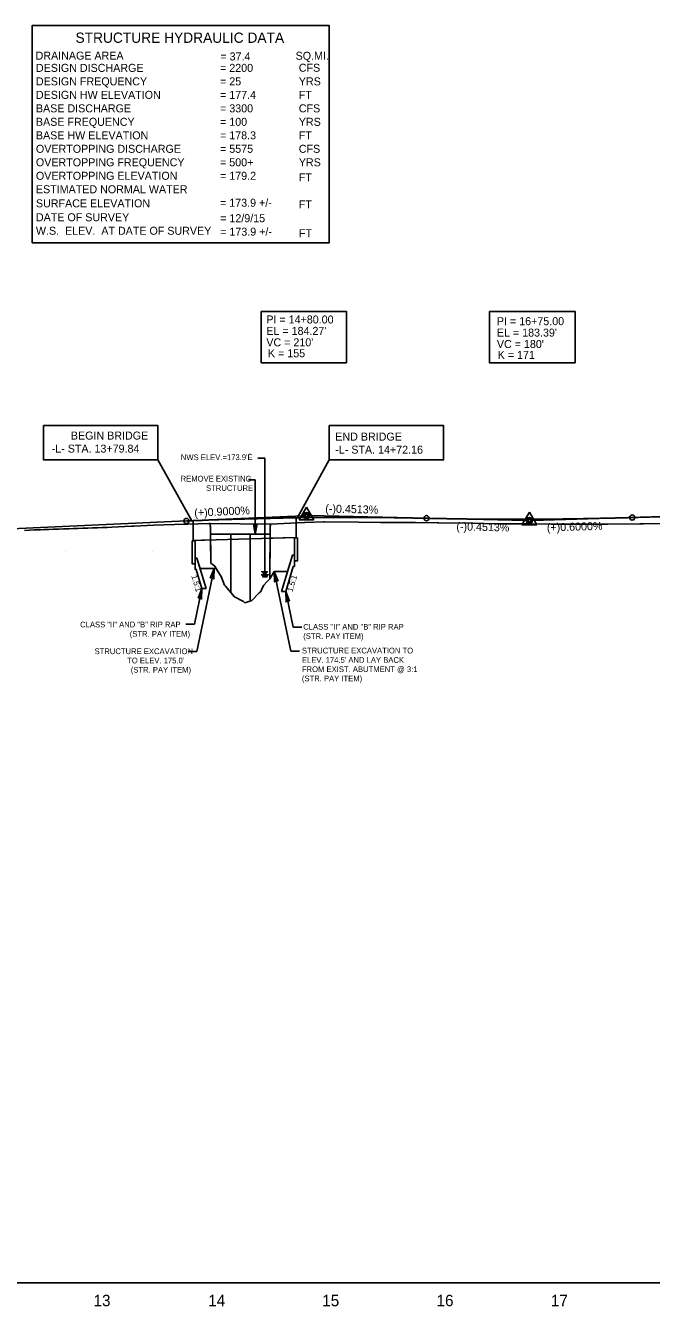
# Model space of a CAD drawing. Extents: x 1726619 to 1729848, y 535683 to 539687.
# Drawn here: x 1728544 to 1729092, y 537992 to 539113 of the extents above; entities that cross this region are included whole.
import ezdxf

# ---------------------------------------------------------------- set-up
doc = ezdxf.new("R2010")
doc.units = 0
for name, color, linetype in [('COGO Default Spiral', 7, 'Continuous'), ('Exist Drainage Structure Bridge', 7, 'Continuous'), ('Exist Profile Cell', 7, 'Continuous'), ('Exist Vertical Profile Horizontal Axis Label Major', 7, 'Continuous'), ('Exist Vertical Profile Horizontal Axis Label Minor', 7, 'Continuous'), ('Exist Vertical Profile Vertical Axis Label', 7, 'Continuous'), ('Prop Dimension', 7, 'Continuous'), ('Prop Dimension Text', 7, 'Continuous'), ('Prop Drainage Structure Bridge Opening Label', 7, 'Continuous'), ('Prop PFL Structure Hydraulic Data Label CELL', 7, 'Continuous'), ('Prop Terminator CELL', 7, 'Continuous'), ('Prop Vertical Profile Grade', 7, 'Continuous'), ('Raster_Level_0', 7, 'Continuous'), ('Sheet Cutting Line CELL', 7, 'Continuous'), ('Sheet Profile CELL', 7, 'Continuous'), ('Sheet Profile Grid Major CELL', 7, 'Continuous'), ('Sheet Profile Grid Middle CELL', 7, 'Continuous'), ('Sheet Profile Grid Minor CELL', 7, 'Continuous'), ('Sheet Sticker Incomplete CELL', 7, 'Continuous')]:
    doc.layers.add(name, color=color, linetype=linetype)

msp = doc.modelspace()

# ---------------------------------------------------------------- linework, layer by layer
at = {"layer": 'COGO Default Spiral'}
for p, q in [((1728747.4, 538734.4), (1728753.4, 538734.4)), ((1728753.4, 538632.5), (1728753.4, 538734.4)), ((1728745.1, 538715.5), (1728739.2, 538715.5)), ((1728745.1, 538668), (1728745.1, 538715.5))]:
    msp.add_line(p, q, dxfattribs=at)
for points in [[(1728753.4, 538632.5), (1728756.5, 538632.5), (1728750.4, 538632.5)], [(1728753.4, 538631.6), (1728755.8, 538631.6), (1728751, 538631.6)], [(1728753.4, 538630.7), (1728755.3, 538630.7), (1728751.5, 538630.7)]]:
    msp.add_lwpolyline(points, dxfattribs=at)
msp.add_lwpolyline([(1728753.4, 538632.5), (1728750.8, 538635.1), (1728755.7, 538635.1)], close=True, dxfattribs=at)
at = {"layer": 'Exist Drainage Structure Bridge'}
for p, q in [((1728705.6, 538677.4), (1728758.4, 538676.9)), ((1728706, 538668), (1728758.1, 538668)), ((1728723.6, 538616.8), (1728723.6, 538668)), ((1728740.6, 538609.6), (1728740.6, 538668))]:
    msp.add_line(p, q, dxfattribs=at)
at = {"layer": 'Exist Profile Cell'}
msp.add_line((1728309.9, 538013), (1729848.2, 538013), dxfattribs=at)
at = {"layer": 'Exist Vertical Profile Horizontal Axis Label Major'}
msp.add_line((1728439.9, 538668.6), (1728684.9, 538679.6), dxfattribs=at)
for points in [[(1728684.9, 538679.6), (1728689.1, 538679.8), (1728693.3, 538680), (1728697.5, 538680.1), (1728701.7, 538680.3), (1728705.9, 538680.5), (1728710.1, 538680.6), (1728714.3, 538680.8), (1728718.5, 538680.9), (1728722.7, 538681.1), (1728726.9, 538681.2), (1728731.1, 538681.3), (1728735.3, 538681.5), (1728739.5, 538681.6), (1728743.7, 538681.7), (1728747.9, 538681.8), (1728752.1, 538681.9), (1728756.3, 538682), (1728760.5, 538682.1), (1728764.7, 538682.2), (1728768.9, 538682.2), (1728773.1, 538682.3), (1728777.3, 538682.4), (1728781.5, 538682.4), (1728785.7, 538682.5), (1728789.9, 538682.5), (1728794.1, 538682.6), (1728798.3, 538682.6), (1728802.5, 538682.7), (1728806.7, 538682.7), (1728810.9, 538682.7), (1728815.1, 538682.7), (1728819.3, 538682.7), (1728823.5, 538682.7), (1728827.7, 538682.7), (1728831.9, 538682.7), (1728836.1, 538682.7), (1728840.3, 538682.7), (1728844.5, 538682.7), (1728848.7, 538682.7), (1728852.9, 538682.6), (1728857.1, 538682.6), (1728861.3, 538682.5), (1728865.5, 538682.5), (1728869.7, 538682.4), (1728873.9, 538682.4), (1728878.1, 538682.3), (1728882.3, 538682.2), (1728886.5, 538682.1), (1728890.7, 538682), (1728894.9, 538682)], [(1728894.9, 538682), (1728898.5, 538681.9), (1728902.1, 538681.8), (1728905.7, 538681.7), (1728909.3, 538681.7), (1728912.9, 538681.6), (1728916.5, 538681.5), (1728920.1, 538681.5), (1728923.7, 538681.4), (1728927.3, 538681.4), (1728930.9, 538681.3), (1728934.5, 538681.3), (1728938.1, 538681.3), (1728941.7, 538681.2), (1728945.3, 538681.2), (1728948.9, 538681.2), (1728952.5, 538681.1), (1728956.1, 538681.1), (1728959.7, 538681.1), (1728963.3, 538681.1), (1728966.9, 538681.1), (1728970.5, 538681.1), (1728974.1, 538681.1), (1728977.7, 538681.1), (1728981.3, 538681.1), (1728984.9, 538681.1), (1728988.5, 538681.1), (1728992.1, 538681.1), (1728995.7, 538681.2), (1728999.3, 538681.2), (1729002.9, 538681.2), (1729006.5, 538681.3), (1729010.1, 538681.3), (1729013.7, 538681.3), (1729017.3, 538681.4), (1729020.9, 538681.4), (1729024.5, 538681.5), (1729028.1, 538681.5), (1729031.7, 538681.6), (1729035.3, 538681.7), (1729038.9, 538681.7), (1729042.5, 538681.8), (1729046.1, 538681.9), (1729049.7, 538682), (1729053.3, 538682), (1729056.9, 538682.1), (1729060.5, 538682.2), (1729064.1, 538682.3), (1729067.7, 538682.4), (1729071.3, 538682.5), (1729074.9, 538682.6)], [(1729074.9, 538682.6), (1729081.7, 538682.8), (1729088.5, 538683), (1729095.3, 538683.2), (1729102.1, 538683.3), (1729108.9, 538683.5), (1729115.7, 538683.6), (1729122.5, 538683.7), (1729129.3, 538683.8), (1729136.1, 538683.8), (1729142.9, 538683.9), (1729149.7, 538683.9), (1729156.5, 538684), (1729163.3, 538684), (1729170.1, 538684), (1729176.9, 538684), (1729183.7, 538683.9), (1729190.5, 538683.9), (1729197.3, 538683.8), (1729204.1, 538683.8), (1729210.9, 538683.7), (1729217.7, 538683.6), (1729224.5, 538683.4), (1729231.3, 538683.3), (1729238.1, 538683.1), (1729244.9, 538683), (1729251.7, 538682.8), (1729258.5, 538682.6), (1729265.3, 538682.4), (1729272.1, 538682.1), (1729278.9, 538681.9), (1729285.7, 538681.6), (1729292.5, 538681.4), (1729299.3, 538681.1), (1729306.1, 538680.8), (1729312.9, 538680.4), (1729319.7, 538680.1), (1729326.5, 538679.8), (1729333.3, 538679.4), (1729340.1, 538679), (1729346.9, 538678.6), (1729353.7, 538678.2), (1729360.5, 538677.8), (1729367.3, 538677.3), (1729374.1, 538676.9), (1729380.9, 538676.4), (1729387.7, 538675.9), (1729394.5, 538675.4), (1729401.3, 538674.9), (1729408.1, 538674.4), (1729414.9, 538673.8)]]:
    msp.add_spline(points, degree=3, dxfattribs=at)
at = {"layer": 'Exist Vertical Profile Horizontal Axis Label Minor'}
for p, q in [((1728579.2, 538653.1), (1728579.2, 538653.1)), ((1728655.6, 538653.1), (1728655.6, 538653.1))]:
    msp.add_line(p, q, dxfattribs=at)
at = {"layer": 'Exist Vertical Profile Vertical Axis Label'}
for p, q in [((1728659.9, 538733), (1728689.7, 538679.8)), ((1728809.9, 538733), (1728782.1, 538682.5)), ((1729074.9, 538682.6), (1729242.1, 538687.6)), ((1728684.9, 538679.6), (1728787.1, 538684.2)), ((1728894.9, 538682), (1728792.6, 538684.3)), ((1728894.9, 538682), (1728982.1, 538680)), ((1729074.9, 538682.6), (1728987.6, 538680))]:
    msp.add_line(p, q, dxfattribs=at)
for centre in [(1728789.9, 538684.3), (1728984.9, 538679.9)]:
    msp.add_circle(centre, 2.75, dxfattribs=at)
at = {"layer": 'Prop Dimension'}
for p, q in [((1728709.1, 538638), (1728694, 538565.5)), ((1728761.7, 538635.5), (1728776.3, 538565.6)), ((1728698.5, 538620.5), (1728692, 538589.2)), ((1728771.7, 538618), (1728778.3, 538586.7)), ((1728692, 538589.2), (1728684.4, 538589.2)), ((1728778.3, 538586.7), (1728785.8, 538586.7)), ((1728694, 538565.5), (1728686.4, 538565.5)), ((1728776.3, 538565.6), (1728783.8, 538565.6))]:
    msp.add_line(p, q, dxfattribs=at)
at = {"layer": 'Prop Terminator CELL'}
for points in [[(1728743.7, 538677), (1728745.1, 538668), (1728746.9, 538677), (1728745.3, 538675.9)], [(1728705.7, 538629.5), (1728709.1, 538638), (1728708.8, 538628.8), (1728707.5, 538630.2)], [(1728765.1, 538627), (1728761.7, 538635.5), (1728762, 538626.3), (1728763.3, 538627.7)], [(1728695.2, 538612), (1728698.5, 538620.5), (1728698.2, 538611.3), (1728696.9, 538612.7)], [(1728775.1, 538609.5), (1728771.7, 538618), (1728772, 538608.8), (1728773.4, 538610.2)]]:
    msp.add_lwpolyline(points, close=True, dxfattribs=at)
at = {"layer": 'Prop Vertical Profile Grade'}
msp.add_lwpolyline([(1728543.2, 538671.4), (1728547.5, 538671.5), (1728551.7, 538671.7), (1728556, 538671.8), (1728557.2, 538671.9), (1728560.2, 538672), (1728564.5, 538672.1), (1728568.7, 538672.3), (1728573, 538672.5), (1728577.2, 538672.6), (1728581.5, 538672.8), (1728582, 538672.8), (1728585.7, 538672.9), (1728590, 538673.1), (1728594.2, 538673.2), (1728598.5, 538673.4), (1728602.7, 538673.5), (1728607, 538673.7), (1728611.2, 538673.8), (1728615.5, 538674), (1728619.7, 538674.2), (1728636.7, 538675), (1728639.2, 538675), (1728656.1, 538675.8), (1728683.6, 538676.7), (1728686.1, 538676.8), (1728704.4, 538677.4), (1728705.6, 538677.4), (1728705.7, 538674.8), (1728706, 538674.8), (1728706.1, 538642.7), (1728709.6, 538640), (1728712.1, 538635.9), (1728715.3, 538630.9), (1728718.2, 538623.5), (1728719, 538622.6), (1728726.8, 538613.2), (1728734.8, 538609), (1728736.1, 538608), (1728742.2, 538610.1), (1728748.4, 538616.7), (1728750.1, 538617.8), (1728751.5, 538621.3), (1728752.7, 538623.4), (1728755, 538626), (1728757.9, 538629.1), (1728758.1, 538675.4), (1728758.4, 538675.2), (1728758.4, 538676.9), (1728787.9, 538678.2), (1728788.4, 538678.2), (1728805.2, 538678.9), (1728805.5, 538678.9), (1728806.1, 538678.9), (1728835.5, 538678.6), (1728855, 538678.4), (1728855.4, 538678.4), (1728884.8, 538678.2), (1728885.4, 538678.2), (1728904.5, 538678.1), (1728905, 538678.1), (1728905.7, 538678.1), (1728935, 538677.6), (1728935.5, 538677.6), (1728954.6, 538677.2), (1728955.6, 538677.2), (1728984.6, 538677), (1728985.3, 538677), (1729004, 538676.9), (1729004.9, 538676.9), (1729033.9, 538676.9), (1729034.9, 538676.9), (1729053.5, 538676.9), (1729081.6, 538677.1), (1729083.5, 538677.1), (1729084.8, 538677.2), (1729103.1, 538677.3)], dxfattribs=at)
at = {"layer": 'Raster_Level_0'}
for p, q in [((1728780.9, 538665.1), (1728758.1, 538664.5)), ((1728780.9, 538664.7), (1728780.9, 538665.1)), ((1728706, 538663), (1728690.9, 538662.6)), ((1728690.9, 538662.6), (1728690.9, 538662.2)), ((1728710.9, 538638), (1728696.9, 538638)), ((1728696.9, 538638), (1728710.9, 538638)), ((1728757.9, 538629.1), (1728761.7, 538635.5)), ((1728757.9, 538629.1), (1728761.7, 538635.5)), ((1728761.7, 538635.5), (1728773.4, 538635.5)), ((1728761.7, 538635.5), (1728773.4, 538635.5)), ((1728698.5, 538620.5), (1728702.1, 538620.5)), ((1728768.1, 538618), (1728771.7, 538618))]:
    msp.add_line(p, q, dxfattribs=at)
for points in [[(1728758.1, 538664.5), (1728757.9, 538629.1)], [(1728779.3, 538649.7), (1728779.3, 538664.7), (1728780.9, 538664.7)], [(1728690.9, 538662.2), (1728692.5, 538662.2), (1728692.5, 538647.2)], [(1728710.9, 538638), (1728709.6, 538640), (1728706.1, 538642.7), (1728706, 538663)], [(1728702.1, 538620.5), (1728694.1, 538647.2), (1728692.5, 538647.2), (1728692.5, 538637.2), (1728693.5, 538637.2), (1728698.5, 538620.5)], [(1728692.5, 538647.2), (1728694.1, 538647.2), (1728696.9, 538638)], [(1728768.1, 538618), (1728777.7, 538649.7), (1728779.3, 538649.7), (1728779.3, 538639.7), (1728778.3, 538639.7), (1728771.7, 538618)], [(1728773.4, 538635.5), (1728777.7, 538649.7), (1728779.3, 538649.7)]]:
    msp.add_lwpolyline(points, dxfattribs=at)
at = {"layer": 'Sheet Profile CELL'}
for p, q in [((1728789.9, 538691.8), (1728783.4, 538680.6)), ((1728789.9, 538691.8), (1728796.4, 538680.6)), ((1728984.9, 538687.4), (1728978.4, 538676.2)), ((1728984.9, 538687.4), (1728991.4, 538676.2)), ((1728783.4, 538680.6), (1728796.4, 538680.6)), ((1728978.4, 538676.2), (1728991.4, 538676.2))]:
    msp.add_line(p, q, dxfattribs=at)
for centre, radius in [((1728789.9, 538684.3), 1.75), ((1728789.9, 538684.3), 1.2), ((1728984.9, 538679.9), 1.75), ((1728984.9, 538679.9), 1.2)]:
    msp.add_circle(centre, radius, dxfattribs=at)
at = {"layer": 'Sheet Profile Grid Major CELL'}
for points in [[(1728549.9, 538923), (1728809.9, 538923), (1728809.9, 539113), (1728549.9, 539113)], [(1728750.4, 538863), (1728824.9, 538863), (1728824.9, 538818), (1728750.4, 538818)], [(1728949.9, 538863), (1729024.9, 538863), (1729024.9, 538818), (1728949.9, 538818)], [(1728559.9, 538763), (1728659.9, 538763), (1728659.9, 538733), (1728559.9, 538733)], [(1728809.9, 538763), (1728909.9, 538763), (1728909.9, 538733), (1728809.9, 538733)]]:
    msp.add_lwpolyline(points, close=True, dxfattribs=at)
at = {"layer": 'Sheet Profile Grid Middle CELL'}
for p, q in [((1728780.9, 538682.4), (1728690.9, 538679.9)), ((1728690.9, 538679.9), (1728690.9, 538662.6)), ((1728780.9, 538682.4), (1728780.9, 538665.1)), ((1728690.9, 538662.6), (1728780.9, 538665.1)), ((1728780.9, 538664.7), (1728780.9, 538665.1)), ((1728690.9, 538662.2), (1728690.9, 538662.6))]:
    msp.add_line(p, q, dxfattribs=at)
for points in [[(1728779.3, 538644.7), (1728782, 538644.7), (1728782, 538664.7), (1728779.3, 538664.7)], [(1728689.8, 538662.2), (1728692.5, 538662.2), (1728692.5, 538642.2), (1728689.8, 538642.2)]]:
    msp.add_lwpolyline(points, close=True, dxfattribs=at)
at = {"layer": 'Sheet Profile Grid Minor CELL'}
for centre in [(1728684.9, 538679.6), (1728894.9, 538682), (1728894.9, 538682), (1729074.9, 538682.6), (1729074.9, 538682.6)]:
    msp.add_circle(centre, 2.25, dxfattribs=at)

# ---------------------------------------------------------------- texts
at = {"layer": 'COGO Default Spiral'}
msp.add_text("NWS ELEV.=173.9'È", height=5, rotation=0.0449, dxfattribs=at).set_placement((1728680, 538732.8))
at = {"layer": 'Exist Vertical Profile Vertical Axis Label'}
for s, p in [('PI = 14+80.00', (1728754.8, 538852.4)), ('PI = 16+75.00', (1728956.5, 538850.9)), ("EL = 184.27'", (1728754.8, 538842.4)), ("EL = 183.39'", (1728956.5, 538840.9))]:
    msp.add_text(s, height=7, dxfattribs=at).set_placement(p)
at = {"layer": 'Prop Dimension Text'}
for s, p in [('REMOVE EXISTING', (1728679.8, 538714.1)), ('STRUCTURE', (1728702, 538705.9)), ('STRUCTURE EXCAVATION TO ', (1728785.9, 538563.7)), ("ELEV. 174.5' AND LAY BACK ", (1728785.9, 538555.5)), ('FROM EXIST. ABUTMENT @ 3:1', (1728785.9, 538547.4)), ('(STR. PAY ITEM)', (1728785.9, 538539.3))]:
    msp.add_text(s, height=5, rotation=360, dxfattribs=at).set_placement(p)
for s, p in [('CLASS "II" AND "B" RIP RAP', (1728591.9, 538586.5)), ('CLASS "II" AND "B" RIP RAP', (1728787.1, 538584.5)), ('(STR. PAY ITEM)', (1728635.3, 538578.3)), ('(STR. PAY ITEM)', (1728787.1, 538576.4)), ('STRUCTURE EXCAVATION ', (1728604.5, 538563.1)), ("TO ELEV. 175.0'", (1728633, 538555)), ('(STR. PAY ITEM)', (1728636.2, 538546.9))]:
    msp.add_text(s, height=5, dxfattribs=at).set_placement(p)
at = {"layer": 'Prop Drainage Structure Bridge Opening Label'}
for rotation, p in [(286.6992, (1728689.1, 538631.4)), (73.3008, (1728777.6, 538617.2))]:
    msp.add_text('1.5:1', height=5, rotation=rotation, dxfattribs=at).set_placement(p)
at = {"layer": 'Prop PFL Structure Hydraulic Data Label CELL'}
for s, height, p in [('STRUCTURE HYDRAULIC DATA', 9, (1728587.8, 539097.9)), ('DRAINAGE AREA', 7, (1728552.9, 539083.2)), ('SQ.MI.', 7, (1728780.4, 539083.1)), ('DESIGN DISCHARGE', 7, (1728553.2, 539072.5)), ('= 2200', 7, (1728714.3, 539072.5)), ('= 37.4', 7, (1728714.6, 539082.5)), ('CFS', 7, (1728783.2, 539072.6)), ('DESIGN FREQUENCY', 7, (1728553.2, 539060.7)), ('= 25', 7, (1728714.3, 539060.7)), ('YRS', 7, (1728783.2, 539060.7)), ('DESIGN HW ELEVATION', 7, (1728553.2, 539048.9)), ('= 177.4', 7, (1728714.3, 539048.9)), ('FT', 7, (1728783.2, 539048.9)), ('BASE DISCHARGE', 7, (1728553.2, 539037.1)), ('= 3300', 7, (1728714.3, 539037.1)), ('CFS', 7, (1728783.2, 539037.1)), ('BASE FREQUENCY', 7, (1728553.2, 539025.3)), ('= 100', 7, (1728714.3, 539025.3)), ('YRS', 7, (1728783.2, 539025.3)), ('BASE HW ELEVATION', 7, (1728553.2, 539013.5)), ('= 178.3', 7, (1728714.3, 539013.5)), ('FT', 7, (1728783.2, 539013.5)), ('OVERTOPPING DISCHARGE', 7, (1728553.2, 539001.7)), ('= 5575', 7, (1728714.3, 539001.7)), ('CFS', 7, (1728783.2, 539001.7)), ('OVERTOPPING FREQUENCY', 7, (1728553.2, 538989.9)), ('= 500+', 7, (1728714.3, 538989.9)), ('YRS', 7, (1728783.2, 538989.9)), ('OVERTOPPING ELEVATION', 7, (1728553.2, 538978.1)), ('= 179.2', 7, (1728714.3, 538978.1)), ('FT', 7, (1728783.2, 538976.7)), ('ESTIMATED NORMAL WATER', 7, (1728553.2, 538966.3)), ('SURFACE ELEVATION', 7, (1728553.2, 538954)), ('= 173.9 +/-', 7, (1728714.3, 538954.5)), ('FT', 7, (1728783.2, 538953.1)), ('FT', 7, (1728783.2, 538953.1)), ('DATE OF SURVEY  ', 7, (1728553.2, 538941.8)), ('= 12/9/15', 7, (1728714.4, 538941)), ('W.S.  ELEV.  AT DATE OF SURVEY', 7, (1728553.2, 538930)), ('= 173.9 +/-', 7, (1728714.4, 538929.2)), ('FT', 7, (1728783.3, 538927.8))]:
    msp.add_text(s, height=height, dxfattribs=at).set_placement(p)
at = {"layer": 'Sheet Cutting Line CELL'}
for s, p in [('13', (1728603.6, 537992.6)), ('14', (1728703.9, 537992.6)), ('15', (1728803.7, 537992.6)), ('16', (1728903.7, 537992.6)), ('17', (1729003.7, 537992.6))]:
    msp.add_text(s, height=10, dxfattribs=at).set_placement(p)
at = {"layer": 'Sheet Profile Grid Minor CELL'}
for s, p in [("VC = 210'", (1728754.8, 538832.4)), ("VC = 180'", (1728956.5, 538830.9)), ('K = 155', (1728756.2, 538822.8)), ('K = 171', (1728957.2, 538821.4)), ('BEGIN BRIDGE', (1728583.8, 538750.8)), ('END BRIDGE', (1728815.1, 538749.9)), ('-L- STA. 13+79.84', (1728567, 538739.4)), ('-L- STA. 14+72.16', (1728815.1, 538738.5))]:
    msp.add_text(s, height=7, dxfattribs=at).set_placement(p)
at = {"layer": 'Sheet Sticker Incomplete CELL'}
for s, rotation, p in [('(+)0.9000%', 2.5766, (1728691.9, 538683.3)), ('(-)0.4513%', 358.7074, (1728806.3, 538687)), ('(-)0.4513%', 358.7074, (1728921, 538671.4)), ('(+)0.6000%', 1.7184, (1729000.3, 538670.4))]:
    msp.add_text(s, height=7, rotation=rotation, dxfattribs=at).set_placement(p)

doc.saveas('drawing.dxf')
